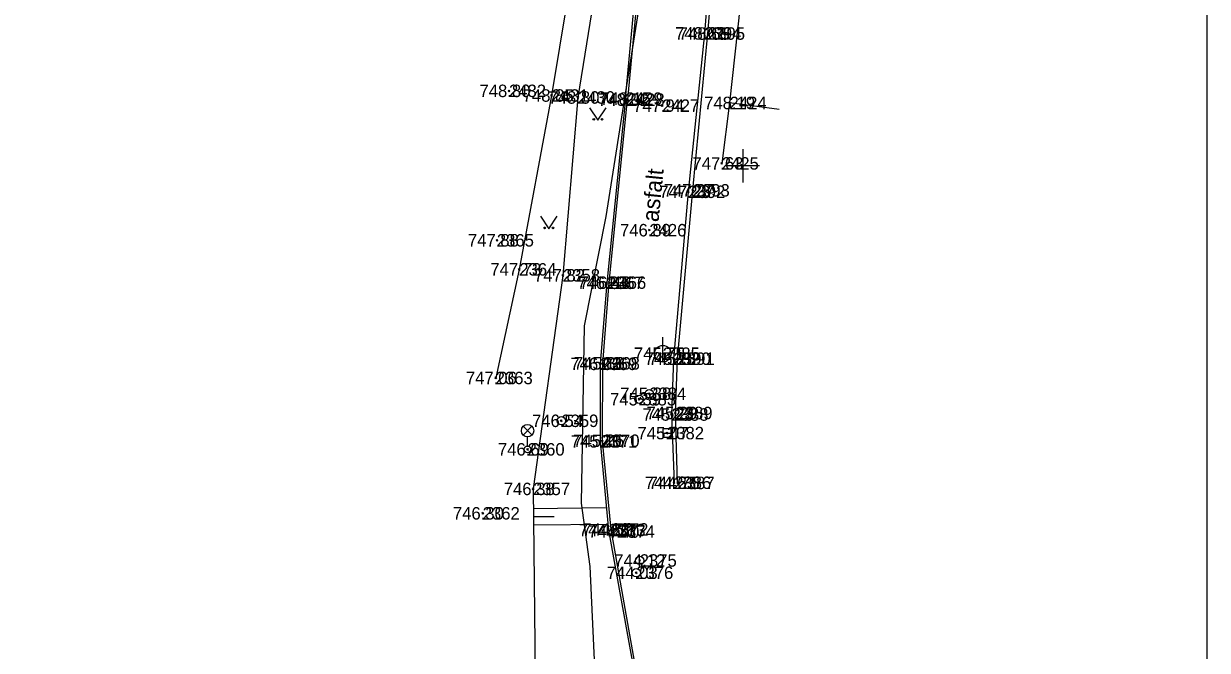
# Model space of a CAD drawing. Extents: x -844765 to -843273, y -997542 to -995529.
# Drawn here: x -844693.3 to -844622, y -995679.2 to -995641.4 of the extents above; entities that cross this region are included whole.
import ezdxf

# ---------------------------------------------------------------- set-up
doc = ezdxf.new("R2010")
doc.units = 0
for name, color, linetype in [('Benešův rám', 7, 'Continuous'), ('Betonový strop', 7, 'Continuous'), ('Dno', 7, 'Continuous'), ('Doplněk polohopisu', 7, 'Continuous'), ('Groma', 7, 'Continuous'), ('Klenba', 7, 'Continuous'), ('Osa', 7, 'Continuous'), ('Popisy budov', 7, 'Continuous'), ('Přítoky', 7, 'Continuous'), ('Rámeček', 7, 'Continuous'), ('Sítě podzemní nerozlišené', 7, 'Continuous'), ('Vrstva 63', 7, 'Continuous'), ('Výška', 7, 'Continuous'), ('Číslo bodu', 7, 'Continuous'), ('Řezy', 7, 'Continuous')]:
    doc.layers.add(name, color=color, linetype=linetype)

msp = doc.modelspace()

# ---------------------------------------------------------------- linework, layer by layer
at = {"layer": 'Benešův rám'}
msp.add_lwpolyline([(-844648.68, -995637.91), (-844649.81, -995637.98), (-844650.16, -995640.36), (-844650.8, -995646.22)], dxfattribs=at)
at = {"layer": 'Betonový strop'}
for points in [[(-844664.62, -995534.22), (-844664.19, -995548.9), (-844664.11, -995551.46), (-844664.11, -995554.94), (-844664.09, -995556.05), (-844664.03, -995560.43), (-844663.85, -995562.6), (-844663.76, -995565.37), (-844663.63, -995567.81), (-844663.36, -995571.12), (-844662.67, -995574.45), (-844662.62, -995578.07), (-844662.26, -995590.78), (-844660.94, -995602.32), (-844659.22, -995619.99), (-844659.57, -995633.99), (-844661.51, -995645.77), (-844663.46, -995656.24), (-844664.88, -995662.78)], [(-844655.2, -995602.53), (-844654.15, -995606.71), (-844653.21, -995612.7), (-844652.44, -995619.67), (-844651.66, -995625.62), (-844651.43, -995630.78), (-844652.32, -995642.03), (-844653.29, -995651.57), (-844654.17, -995661.62), (-844654.3, -995664.98), (-844654.14, -995669.09)], [(-844653.93, -995669.1), (-844654.06, -995664.89), (-844653.93, -995661.62), (-844653.02, -995651.48), (-844652.1, -995642.04), (-844651.17, -995630.73), (-844651.42, -995625.54), (-844652.13, -995619.65), (-844652.92, -995612.63), (-844653.86, -995606.75), (-844654.95, -995602.54)], [(-844657.06, -995645.96), (-844655.94, -995633.89), (-844656.69, -995619.78), (-844657.75, -995611.74), (-844659.44, -995604.01)], [(-844659.3, -995603.97), (-844657.63, -995611.73), (-844656.55, -995619.84), (-844655.8, -995633.88), (-844656.94, -995646.02)], [(-844659.22, -995619.99), (-844657.95, -995633.56), (-844659.93, -995645.89), (-844660.83, -995656.6), (-844662.63, -995669.46), (-844662.5, -995680.65), (-844666.57, -995688.36), (-844665.42, -995694.87), (-844661.25, -995699.68), (-844662.8, -995702.87)], [(-844657.06, -995645.96), (-844658.19, -995657.05), (-844658.59, -995661.93), (-844658.59, -995666.6), (-844658.09, -995671.94), (-844656.49, -995680.82)], [(-844656.37, -995680.74), (-844657.92, -995671.9), (-844658.45, -995666.56), (-844658.43, -995661.9), (-844658.05, -995657.04), (-844656.94, -995646.02)]]:
    msp.add_lwpolyline(points, dxfattribs=at)
at = {"layer": 'Dno'}
for points in [[(-844659.226, -995646.505), (-844658.726, -995647.255), (-844658.226, -995646.505)], [(-844662.183, -995653.042), (-844661.683, -995653.792), (-844661.183, -995653.042)]]:
    msp.add_lwpolyline(points, dxfattribs=at)
for centre in [(-844658.976, -995647.205), (-844658.476, -995647.205), (-844661.933, -995653.742), (-844661.433, -995653.742)]:
    msp.add_circle(centre, 0.05, dxfattribs=at)
at = {"layer": 'Doplněk polohopisu'}
for p, q in [((-844654.82, -995661.82), (-844654.82, -995660.32)), ((-844654.82, -995666.1), (-844654.32, -995666.1))]:
    msp.add_line(p, q, dxfattribs=at)
msp.add_lwpolyline([(-844654.82, -995666.35), (-844654.32, -995666.35), (-844654.32, -995665.85), (-844654.82, -995665.85)], close=True, dxfattribs=at)
msp.add_circle((-844654.82, -995661.32), 0.5, dxfattribs=at)
at = {"layer": 'Groma'}
for p, q in [((-844663.224, -995666.218), (-844662.696, -995665.69)), ((-844662.688, -995666.215), (-844663.216, -995665.686)), ((-844662.96, -995666.88), (-844662.96, -995666.33))]:
    msp.add_line(p, q, dxfattribs=at)
for centre, radius in [((-844660.93, -995665.36), 0.25), ((-844662.96, -995665.955), 0.375), ((-844662.96, -995667.08), 0.2)]:
    msp.add_circle(centre, radius, dxfattribs=at)
at = {"layer": 'Klenba'}
for p, q in [((-844650.8, -995646.22), (-844651.27, -995649.86)), ((-844647.825, -995646.604), (-844650.8, -995646.22))]:
    msp.add_line(p, q, dxfattribs=at)
at = {"layer": 'Osa'}
msp.add_lwpolyline([(-844658.903, -995680.2), (-844659.185, -995674.135), (-844659.71, -995670.325), (-844659.53, -995659.64), (-844658.235, -995653.065), (-844655.555, -995636.12), (-844654.74, -995623.74), (-844655.415, -995613.92), (-844656.623, -995604.085), (-844657.83, -995594.25), (-844658.533, -995587.498), (-844659.235, -995580.745), (-844660.07, -995563.3), (-844659.88, -995547.705), (-844659.82, -995540.9), (-844659.9, -995538.365), (-844659.78, -995536.68)], dxfattribs=at)
at = {"layer": 'Popisy budov'}
for centre in [(-844656.25, -995664.06), (-844655.64, -995663.73), (-844657.53, -995672.03), (-844656.21, -995673.77), (-844656.42, -995674.51)]:
    msp.add_circle(centre, 0.25, dxfattribs=at)
at = {"layer": 'Přítoky'}
for p, q in [((-844662.616, -995670.633), (-844658.217, -995670.581)), ((-844662.611, -995671.132), (-844661.351, -995671.118)), ((-844662.605, -995671.632), (-844658.124, -995671.58))]:
    msp.add_line(p, q, dxfattribs=at)
at = {"layer": 'Rámeček'}
for p, q in [((-844650, -995649), (-844650, -995651)), ((-844649, -995650), (-844651, -995650))]:
    msp.add_line(p, q, dxfattribs=at)
at = {"layer": 'Sítě podzemní nerozlišené'}
for p, q in [((-844652.32, -995642.03), (-844652.37, -995641.98)), ((-844652.32, -995642.03), (-844652.37, -995642.08)), ((-844652.32, -995642.03), (-844652.27, -995641.98)), ((-844652.32, -995642.03), (-844652.27, -995642.08)), ((-844652.1, -995642.04), (-844652.15, -995641.99)), ((-844652.1, -995642.04), (-844652.15, -995642.09)), ((-844652.1, -995642.04), (-844652.05, -995641.99)), ((-844652.1, -995642.04), (-844652.05, -995642.09)), ((-844664.08, -995645.49), (-844664.13, -995645.44)), ((-844664.08, -995645.49), (-844664.13, -995645.54)), ((-844664.08, -995645.49), (-844664.03, -995645.44)), ((-844664.08, -995645.49), (-844664.03, -995645.54)), ((-844661.51, -995645.77), (-844661.56, -995645.72)), ((-844661.51, -995645.77), (-844661.56, -995645.82)), ((-844661.51, -995645.77), (-844661.46, -995645.72)), ((-844661.51, -995645.77), (-844661.46, -995645.82)), ((-844659.93, -995645.89), (-844659.98, -995645.84)), ((-844659.93, -995645.89), (-844659.98, -995645.94)), ((-844659.93, -995645.89), (-844659.88, -995645.84)), ((-844659.93, -995645.89), (-844659.88, -995645.94)), ((-844657.06, -995645.96), (-844657.11, -995645.91)), ((-844657.06, -995645.96), (-844657.11, -995646.01)), ((-844657.06, -995645.96), (-844657.01, -995645.91)), ((-844657.06, -995645.96), (-844657.01, -995646.01)), ((-844656.94, -995646.02), (-844656.99, -995645.97)), ((-844656.94, -995646.02), (-844656.99, -995646.07)), ((-844656.94, -995646.02), (-844656.89, -995645.97)), ((-844656.94, -995646.02), (-844656.89, -995646.07)), ((-844654.86, -995646.38), (-844654.91, -995646.33)), ((-844654.86, -995646.38), (-844654.91, -995646.43)), ((-844654.86, -995646.38), (-844654.81, -995646.33)), ((-844654.86, -995646.38), (-844654.81, -995646.43)), ((-844650.8, -995646.22), (-844650.85, -995646.17)), ((-844650.8, -995646.22), (-844650.85, -995646.27)), ((-844650.8, -995646.22), (-844650.75, -995646.17)), ((-844650.8, -995646.22), (-844650.75, -995646.27)), ((-844651.27, -995649.86), (-844651.32, -995649.81)), ((-844651.27, -995649.86), (-844651.32, -995649.91)), ((-844651.27, -995649.86), (-844651.22, -995649.81)), ((-844651.27, -995649.86), (-844651.22, -995649.91)), ((-844653.29, -995651.57), (-844653.34, -995651.52)), ((-844653.29, -995651.57), (-844653.34, -995651.62)), ((-844653.29, -995651.57), (-844653.24, -995651.52)), ((-844653.29, -995651.57), (-844653.24, -995651.62)), ((-844653.02, -995651.48), (-844653.07, -995651.43)), ((-844653.02, -995651.48), (-844653.07, -995651.53)), ((-844653.02, -995651.48), (-844652.97, -995651.43)), ((-844653.02, -995651.48), (-844652.97, -995651.53)), ((-844655.63, -995653.88), (-844655.68, -995653.83)), ((-844655.63, -995653.88), (-844655.68, -995653.93)), ((-844655.63, -995653.88), (-844655.58, -995653.83)), ((-844655.63, -995653.88), (-844655.58, -995653.93)), ((-844664.81, -995654.49), (-844664.86, -995654.44)), ((-844664.81, -995654.49), (-844664.86, -995654.54)), ((-844664.81, -995654.49), (-844664.76, -995654.44)), ((-844664.81, -995654.49), (-844664.76, -995654.54)), ((-844663.46, -995656.24), (-844663.51, -995656.19)), ((-844663.46, -995656.24), (-844663.51, -995656.29)), ((-844663.46, -995656.24), (-844663.41, -995656.19)), ((-844663.46, -995656.24), (-844663.41, -995656.29)), ((-844660.83, -995656.6), (-844660.88, -995656.55)), ((-844660.83, -995656.6), (-844660.88, -995656.65)), ((-844660.83, -995656.6), (-844660.78, -995656.55)), ((-844660.83, -995656.6), (-844660.78, -995656.65)), ((-844658.19, -995657.05), (-844658.24, -995657)), ((-844658.19, -995657.05), (-844658.24, -995657.1)), ((-844658.19, -995657.05), (-844658.14, -995657)), ((-844658.19, -995657.05), (-844658.14, -995657.1)), ((-844658.05, -995657.04), (-844658.1, -995656.99)), ((-844658.05, -995657.04), (-844658.1, -995657.09)), ((-844658.05, -995657.04), (-844658, -995656.99)), ((-844658.05, -995657.04), (-844658, -995657.09)), ((-844654.82, -995661.32), (-844654.87, -995661.27)), ((-844654.82, -995661.32), (-844654.87, -995661.37)), ((-844654.82, -995661.32), (-844654.77, -995661.27)), ((-844654.82, -995661.32), (-844654.77, -995661.37)), ((-844654.17, -995661.62), (-844654.22, -995661.57)), ((-844654.17, -995661.62), (-844654.22, -995661.67)), ((-844654.17, -995661.62), (-844654.12, -995661.57)), ((-844654.17, -995661.62), (-844654.12, -995661.67)), ((-844653.93, -995661.62), (-844653.98, -995661.57)), ((-844653.93, -995661.62), (-844653.98, -995661.67)), ((-844653.93, -995661.62), (-844653.88, -995661.57)), ((-844653.93, -995661.62), (-844653.88, -995661.67)), ((-844658.59, -995661.93), (-844658.64, -995661.88)), ((-844658.59, -995661.93), (-844658.64, -995661.98)), ((-844658.59, -995661.93), (-844658.54, -995661.88)), ((-844658.59, -995661.93), (-844658.54, -995661.98)), ((-844658.43, -995661.9), (-844658.48, -995661.85)), ((-844658.43, -995661.9), (-844658.48, -995661.95)), ((-844658.43, -995661.9), (-844658.38, -995661.85)), ((-844658.43, -995661.9), (-844658.38, -995661.95)), ((-844664.88, -995662.78), (-844664.93, -995662.73)), ((-844664.88, -995662.78), (-844664.93, -995662.83)), ((-844664.88, -995662.78), (-844664.83, -995662.73)), ((-844664.88, -995662.78), (-844664.83, -995662.83)), ((-844655.64, -995663.73), (-844655.69, -995663.68)), ((-844655.64, -995663.73), (-844655.69, -995663.78)), ((-844655.64, -995663.73), (-844655.59, -995663.68)), ((-844655.64, -995663.73), (-844655.59, -995663.78)), ((-844656.25, -995664.06), (-844656.3, -995664.01)), ((-844656.25, -995664.06), (-844656.3, -995664.11)), ((-844656.25, -995664.06), (-844656.2, -995664.01)), ((-844656.25, -995664.06), (-844656.2, -995664.11)), ((-844660.93, -995665.36), (-844660.98, -995665.31)), ((-844660.93, -995665.36), (-844660.88, -995665.31)), ((-844654.3, -995664.98), (-844654.35, -995664.93)), ((-844654.3, -995664.98), (-844654.35, -995665.03)), ((-844654.3, -995664.98), (-844654.25, -995664.93)), ((-844654.3, -995664.98), (-844654.25, -995665.03)), ((-844654.06, -995664.89), (-844654.11, -995664.84)), ((-844654.06, -995664.89), (-844654.11, -995664.94)), ((-844654.06, -995664.89), (-844654.01, -995664.84)), ((-844654.06, -995664.89), (-844654.01, -995664.94)), ((-844660.93, -995665.36), (-844660.98, -995665.41)), ((-844660.93, -995665.36), (-844660.88, -995665.41)), ((-844658.59, -995666.6), (-844658.64, -995666.55)), ((-844658.59, -995666.6), (-844658.64, -995666.65)), ((-844658.59, -995666.6), (-844658.54, -995666.55)), ((-844658.59, -995666.6), (-844658.54, -995666.65)), ((-844658.45, -995666.56), (-844658.5, -995666.51)), ((-844658.45, -995666.56), (-844658.5, -995666.61)), ((-844658.45, -995666.56), (-844658.4, -995666.51)), ((-844658.45, -995666.56), (-844658.4, -995666.61)), ((-844654.57, -995666.1), (-844654.62, -995666.05)), ((-844654.57, -995666.1), (-844654.62, -995666.15)), ((-844654.57, -995666.1), (-844654.52, -995666.05)), ((-844654.57, -995666.1), (-844654.52, -995666.15)), ((-844662.96, -995667.08), (-844663.01, -995667.03)), ((-844662.96, -995667.08), (-844663.01, -995667.13)), ((-844662.96, -995667.08), (-844662.91, -995667.03)), ((-844662.96, -995667.08), (-844662.91, -995667.13)), ((-844662.63, -995669.46), (-844662.68, -995669.41)), ((-844662.63, -995669.46), (-844662.68, -995669.51)), ((-844662.63, -995669.46), (-844662.58, -995669.41)), ((-844662.63, -995669.46), (-844662.58, -995669.51)), ((-844654.14, -995669.09), (-844654.19, -995669.04)), ((-844654.14, -995669.09), (-844654.19, -995669.14)), ((-844654.14, -995669.09), (-844654.09, -995669.04)), ((-844654.14, -995669.09), (-844654.09, -995669.14)), ((-844653.93, -995669.1), (-844653.98, -995669.05)), ((-844653.93, -995669.1), (-844653.98, -995669.15)), ((-844653.93, -995669.1), (-844653.88, -995669.05)), ((-844653.93, -995669.1), (-844653.88, -995669.15)), ((-844665.66, -995670.93), (-844665.71, -995670.88)), ((-844665.66, -995670.93), (-844665.71, -995670.98)), ((-844665.66, -995670.93), (-844665.61, -995670.88)), ((-844665.66, -995670.93), (-844665.61, -995670.98)), ((-844658.09, -995671.94), (-844658.14, -995671.89)), ((-844658.09, -995671.94), (-844658.14, -995671.99)), ((-844658.09, -995671.94), (-844658.04, -995671.89)), ((-844658.09, -995671.94), (-844658.04, -995671.99)), ((-844657.92, -995671.9), (-844657.97, -995671.85)), ((-844657.92, -995671.9), (-844657.97, -995671.95)), ((-844657.92, -995671.9), (-844657.87, -995671.85)), ((-844657.92, -995671.9), (-844657.87, -995671.95)), ((-844657.53, -995672.03), (-844657.58, -995671.98)), ((-844657.53, -995672.03), (-844657.58, -995672.08)), ((-844657.53, -995672.03), (-844657.48, -995671.98)), ((-844657.53, -995672.03), (-844657.48, -995672.08)), ((-844656.21, -995673.77), (-844656.26, -995673.72)), ((-844656.21, -995673.77), (-844656.26, -995673.82)), ((-844656.21, -995673.77), (-844656.16, -995673.72)), ((-844656.21, -995673.77), (-844656.16, -995673.82)), ((-844656.42, -995674.51), (-844656.47, -995674.46)), ((-844656.42, -995674.51), (-844656.47, -995674.56)), ((-844656.42, -995674.51), (-844656.37, -995674.46)), ((-844656.42, -995674.51), (-844656.37, -995674.56))]:
    msp.add_line(p, q, dxfattribs=at)
at = {"layer": 'Vrstva 63'}
msp.add_lwpolyline([(-844622.042, -995719.006), (-844622.042, -995529.006), (-844764.542, -995529.006), (-844764.542, -995719.006)], close=True, dxfattribs=at)

# ---------------------------------------------------------------- texts
at = {"layer": 'Výška'}
msp.add_text('asfalt', height=1, rotation=84.24823, dxfattribs=at).set_placement((-844655.083, -995653.415))
at = {"layer": 'Číslo bodu'}
for s, p in [('2394', (-844652.32, -995642.405)), ('2395', (-844652.1, -995642.415)), ('2432', (-844664.08, -995645.865)), ('2431', (-844661.51, -995646.145)), ('2430', (-844659.93, -995646.265)), ('2429', (-844657.06, -995646.335)), ('2428', (-844656.94, -995646.395)), ('2427', (-844654.86, -995646.755)), ('2424', (-844650.8, -995646.595)), ('2425', (-844651.27, -995650.235)), ('2392', (-844653.29, -995651.945)), ('2393', (-844653.02, -995651.855)), ('2426', (-844655.63, -995654.255)), ('2365', (-844664.81, -995654.865)), ('2364', (-844663.46, -995656.615)), ('2358', (-844660.83, -995656.975)), ('2367', (-844658.19, -995657.425)), ('2366', (-844658.05, -995657.415)), ('2385', (-844654.82, -995661.695)), ('2369', (-844658.59, -995662.305)), ('2368', (-844658.43, -995662.275)), ('2390', (-844654.17, -995661.995)), ('2391', (-844653.93, -995661.995)), ('2363', (-844664.88, -995663.155)), ('2383', (-844656.25, -995664.435)), ('2384', (-844655.64, -995664.105)), ('2388', (-844654.3, -995665.355)), ('2389', (-844654.06, -995665.265)), ('2359', (-844660.93, -995665.735)), ('2382', (-844654.57, -995666.475)), ('2360', (-844662.96, -995667.455)), ('2371', (-844658.59, -995666.975)), ('2370', (-844658.45, -995666.935)), ('2386', (-844654.14, -995669.465)), ('2387', (-844653.93, -995669.475)), ('2357', (-844662.63, -995669.835)), ('2362', (-844665.66, -995671.305)), ('2373', (-844658.09, -995672.315)), ('2372', (-844657.92, -995672.275)), ('2374', (-844657.53, -995672.405)), ('2375', (-844656.21, -995674.145)), ('2376', (-844656.42, -995674.885))]:
    msp.add_text(s, height=0.75, dxfattribs=at).set_placement(p)
at = {"layer": 'Řezy'}
for s, p in [('748.62', (-844654.083, -995642.405)), ('748.65', (-844653.863, -995642.415)), ('748.80', (-844665.855, -995645.865)), ('748.85', (-844663.252, -995646.145)), ('748.80', (-844661.705, -995646.265)), ('748.02', (-844658.714, -995646.395)), ('748.15', (-844658.589, -995646.335)), ('747.94', (-844656.605, -995646.755)), ('748.19', (-844652.332, -995646.595)), ('747.63', (-844653.033, -995650.235)), ('747.23', (-844655.032, -995651.945)), ('747.27', (-844654.762, -995651.855)), ('746.89', (-844657.396, -995654.255)), ('747.88', (-844666.552, -995654.865)), ('747.73', (-844665.202, -995656.615)), ('747.82', (-844662.572, -995656.975)), ('746.64', (-844659.973, -995657.425)), ('746.46', (-844659.833, -995657.415)), ('745.75', (-844656.562, -995661.695)), ('746.02', (-844660.385, -995662.305)), ('745.83', (-844660.172, -995662.275)), ('745.75', (-844655.912, -995661.995)), ('745.82', (-844655.672, -995661.995)), ('747.06', (-844666.675, -995663.155)), ('745.39', (-844657.995, -995664.435)), ('745.38', (-844657.382, -995664.105)), ('745.23', (-844656.042, -995665.355)), ('745.29', (-844655.805, -995665.265)), ('746.54', (-844662.693, -995665.735)), ('745.07', (-844656.344, -995666.475)), ('746.69', (-844664.746, -995667.455)), ('745.40', (-844660.365, -995666.975)), ('745.26', (-844660.213, -995666.935)), ('744.67', (-844655.903, -995669.465)), ('744.75', (-844655.672, -995669.475)), ('746.38', (-844664.393, -995669.835)), ('746.30', (-844667.455, -995671.305)), ('744.66', (-844659.873, -995672.315)), ('744.52', (-844659.662, -995672.275)), ('744.40', (-844659.305, -995672.405)), ('744.12', (-844657.739, -995674.145)), ('744.03', (-844658.194, -995674.885))]:
    msp.add_text(s, height=0.75, dxfattribs=at).set_placement(p)

doc.saveas('drawing.dxf')
